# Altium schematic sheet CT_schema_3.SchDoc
size 396 x 205 mm
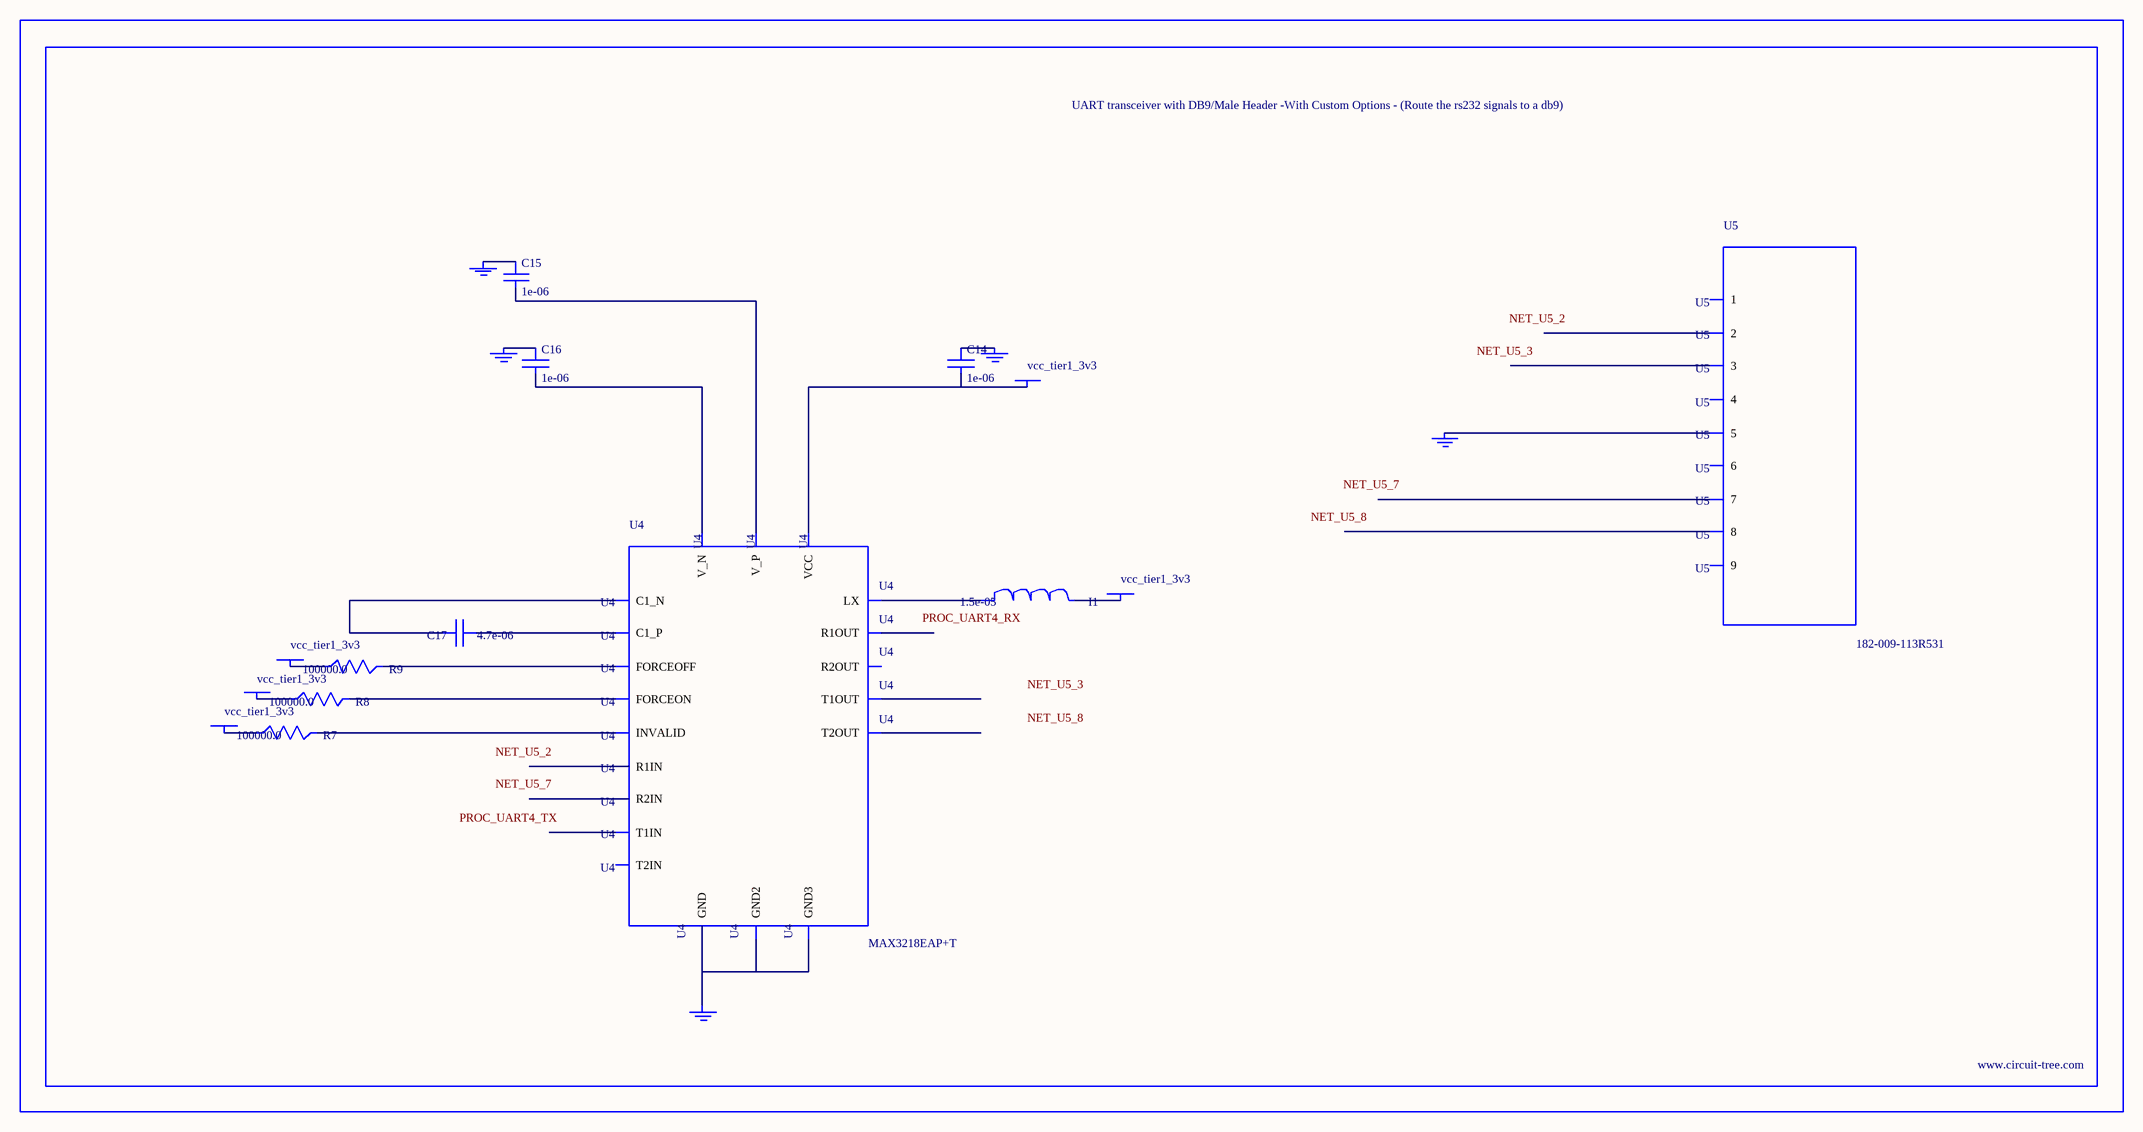
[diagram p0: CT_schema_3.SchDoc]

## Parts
BORDER2  (no value)
C14  1e-06  [C0603]
C15  1e-06  [C0603]
C16  1e-06  [C0603]
C17  4.7e-06  [C0805]
GND_INSTANCE_2_0  (no value)
GND_INSTANCE_2_1  (no value)
GND_INSTANCE_2_2  (no value)
GND_INSTANCE_2_3  (no value)
GND_INSTANCE_2_4  (no value)
I1  1.5e-05  [L1210]
POWER_INSTANCE_2_0  vcc_tier1_3v3
POWER_INSTANCE_2_1  vcc_tier1_3v3
POWER_INSTANCE_2_2  vcc_tier1_3v3
POWER_INSTANCE_2_3  vcc_tier1_3v3
POWER_INSTANCE_2_4  vcc_tier1_3v3
R7  100000.0  [R0603]
R8  100000.0  [R0603]
R9  100000.0  [R0603]
U4  MAX3218EAP+T  [SSOP-20]
U5  182-009-113R531  [182-009-MALE]

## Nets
NetC14_1: C14.1 GND_INSTANCE_2_0.0(GND)
NetC14_2: C14.2 POWER_INSTANCE_2_4.0(PWR) U4.6(VCC)
NetC15_1: C15.1 GND_INSTANCE_2_2.0(GND)
NetC15_2: C15.2 U4.19(V_P)
NetC16_1: C16.1 GND_INSTANCE_2_1.0(GND)
NetC16_2: C16.2 U4.15(V_N)
NetC17_1: C17.1 U4.18(C1_P)
NetC17_2: C17.2 U4.16(C1_N)
NetGND_INSTANCE_2_3_0: GND_INSTANCE_2_3.0(GND) U4.5(GND) U4.17(GND2) U4.20(GND3)
NetGND_INSTANCE_2_4_0: GND_INSTANCE_2_4.0(GND) U5.5
NetI1_1: I1.1 U4.1(LX)
NetI1_2: I1.2 POWER_INSTANCE_2_0.0(PWR)
NetPOWER_INSTANCE_2_1_0: POWER_INSTANCE_2_1.0(PWR) R7.1
NetPOWER_INSTANCE_2_2_0: POWER_INSTANCE_2_2.0(PWR) R8.1
NetPOWER_INSTANCE_2_3_0: POWER_INSTANCE_2_3.0(PWR) R9.1
NetR7_2: R7.2 U4.2(INVALID)
NetR8_2: R8.2 U4.3(FORCEON)
NetR9_2: R9.2 U4.4(FORCEOFF)

Not connected (* = marked no-connect by the designer): U4 7(T1IN) 8(T2IN) 9(R1OUT) 10(R2OUT) 11(R2IN) 12(R1IN) 13(T2OUT) 14(T1OUT); U5 1 2 3 4 6 7 8 9

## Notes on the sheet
- Labels drawn without touching a wire or pin: NET_U5_2, NET_U5_3, NET_U5_7, NET_U5_8, PROC_UART4_RX, PROC_UART4_TX

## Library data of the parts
BORDER2 = BORDER_PAGE2
C14-C16 = C0603C105K3RACTU
C17 = C0805C475K4RACTU
GND_INSTANCE_2_0-GND_INSTANCE_2_4 = GND
I1 = L1210R150MDWIT
POWER_INSTANCE_2_0-POWER_INSTANCE_2_4 = PWR
R7-R9 = RC0603JR-07100KL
